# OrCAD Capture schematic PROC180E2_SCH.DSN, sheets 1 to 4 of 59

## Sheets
1 39. DIGITAL AUDIO IN_OUT-2: size C; title: AUDIO -  DIGITAL IN & OUT, OPTICAL IN -2; rev: E2
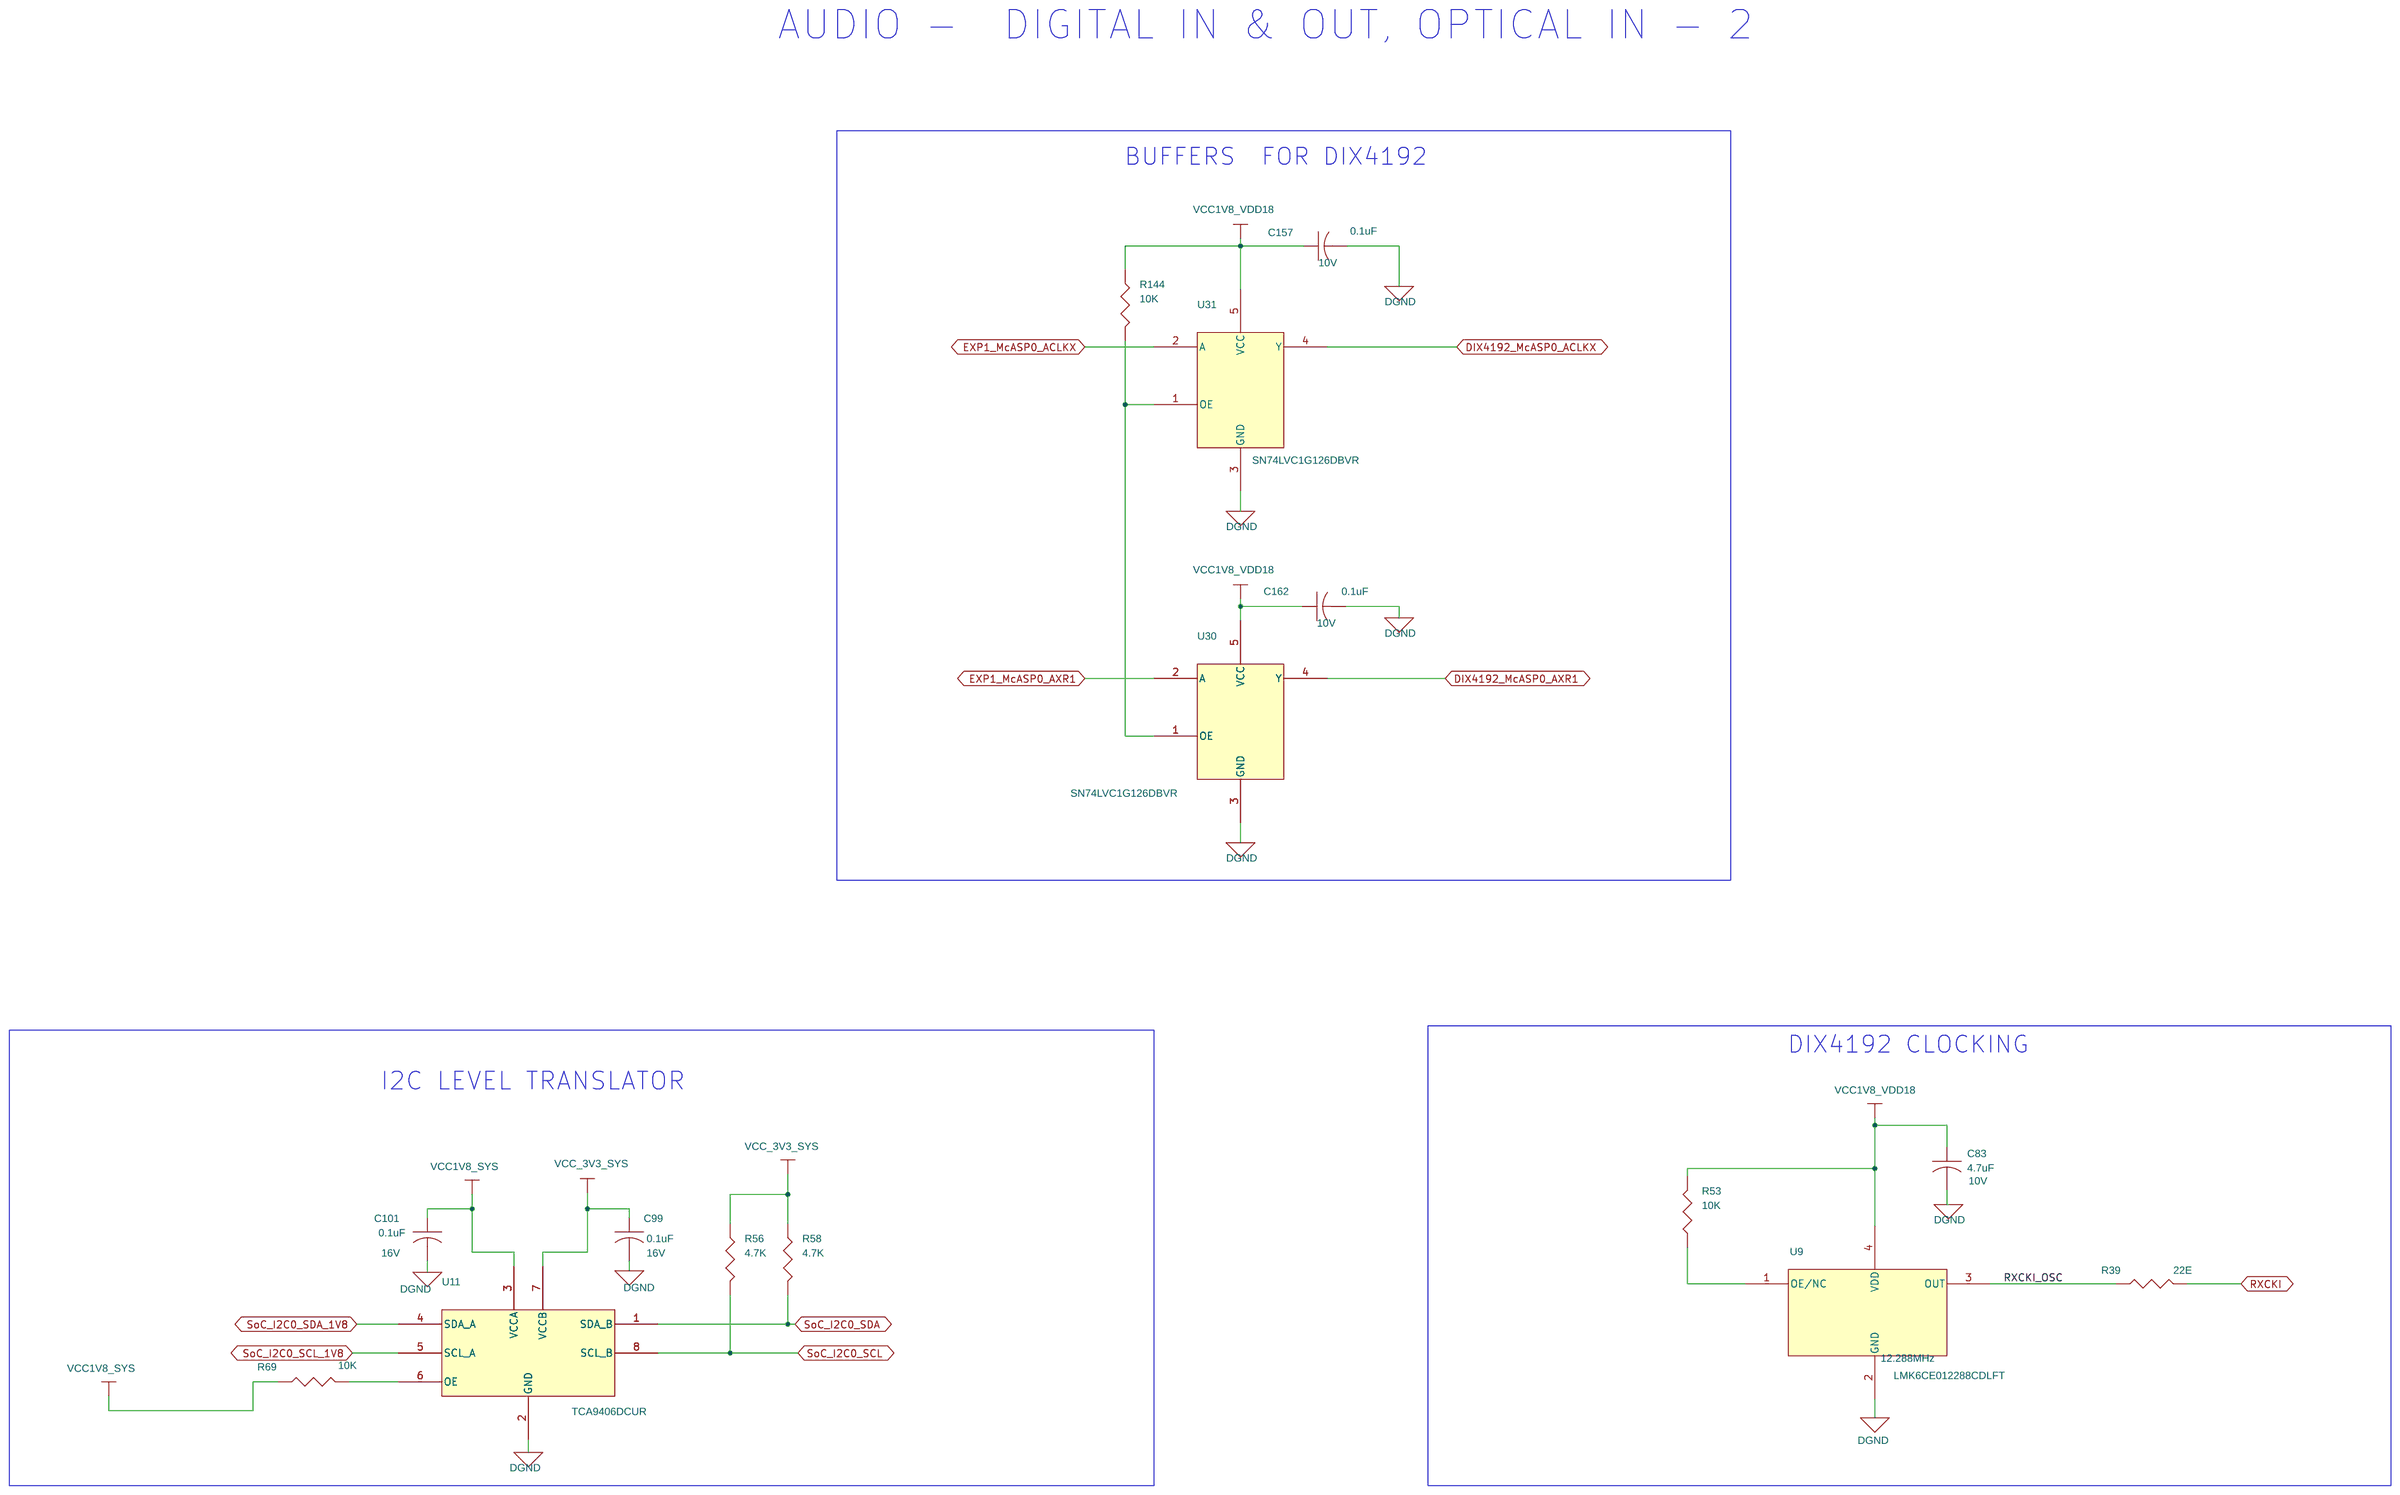
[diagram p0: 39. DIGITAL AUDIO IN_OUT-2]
2 14. SOC POWER SUPPLY PMIC - 2: size C; title: SOC POWER SUPPLY PMIC - 2
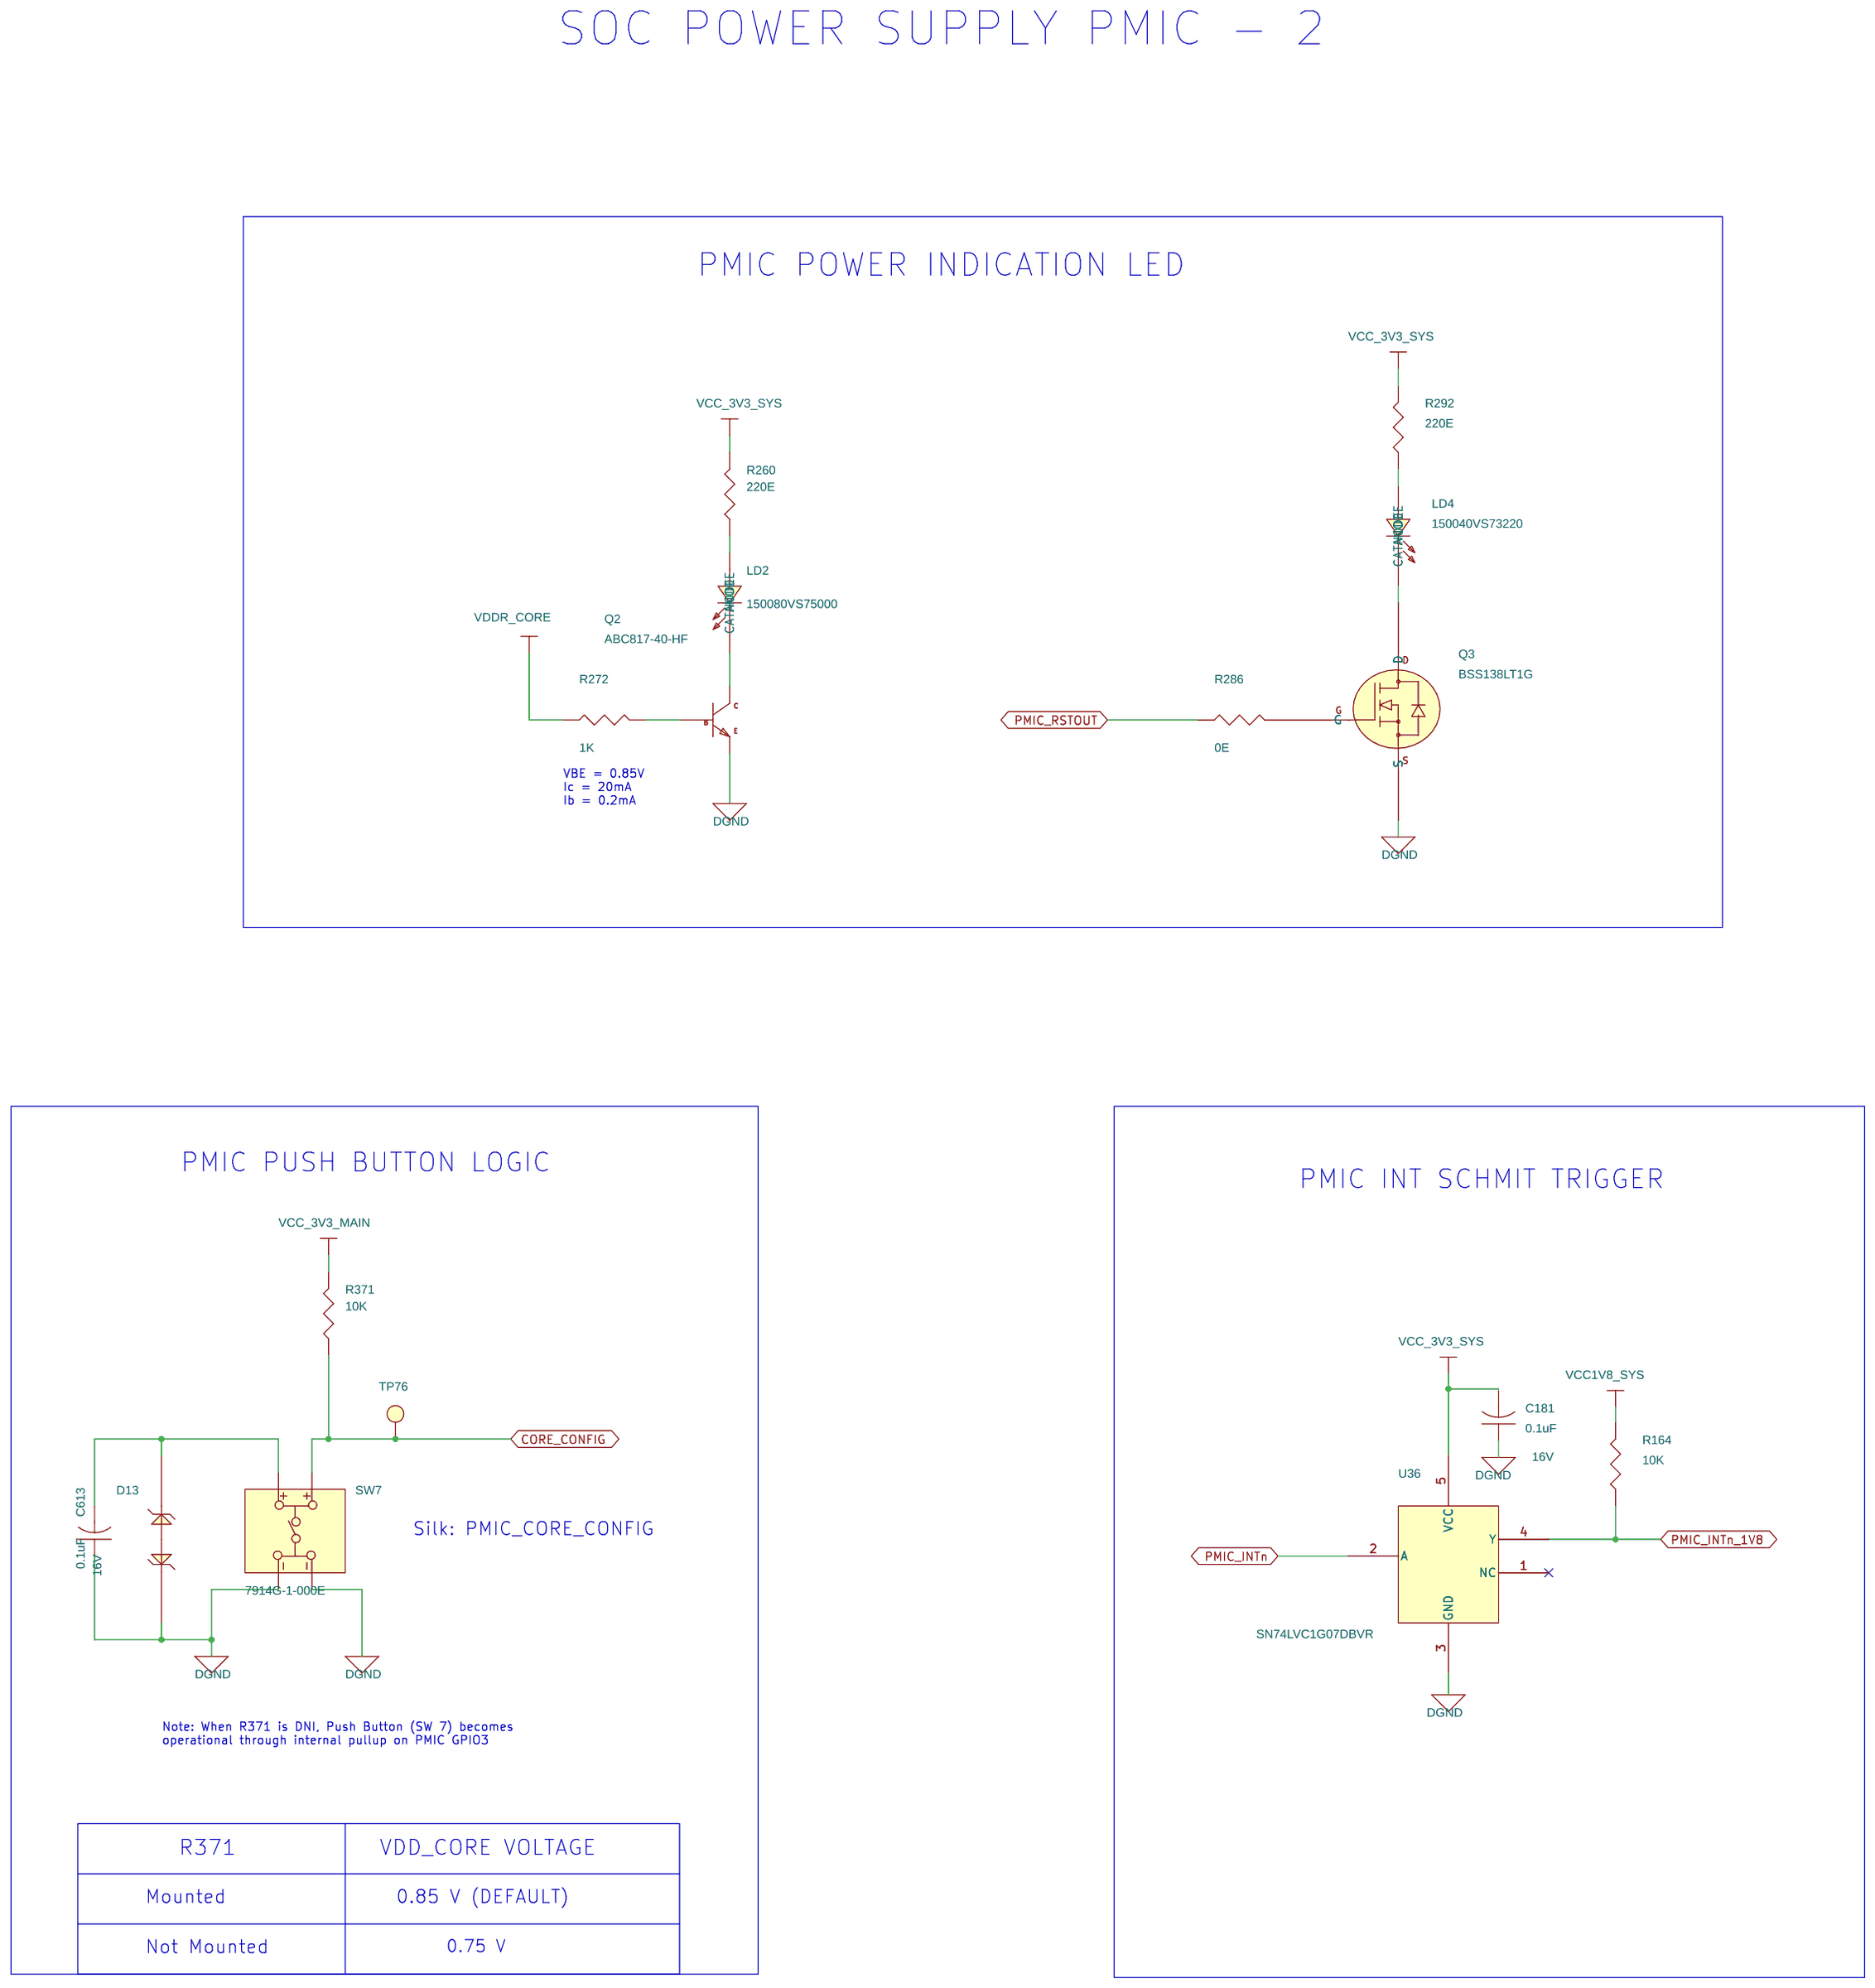
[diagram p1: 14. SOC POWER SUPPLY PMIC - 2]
3 57. TEST AUTOMATION BUFFERS: size C; title: XDS110 TEST AUTOMATION BUFFERS
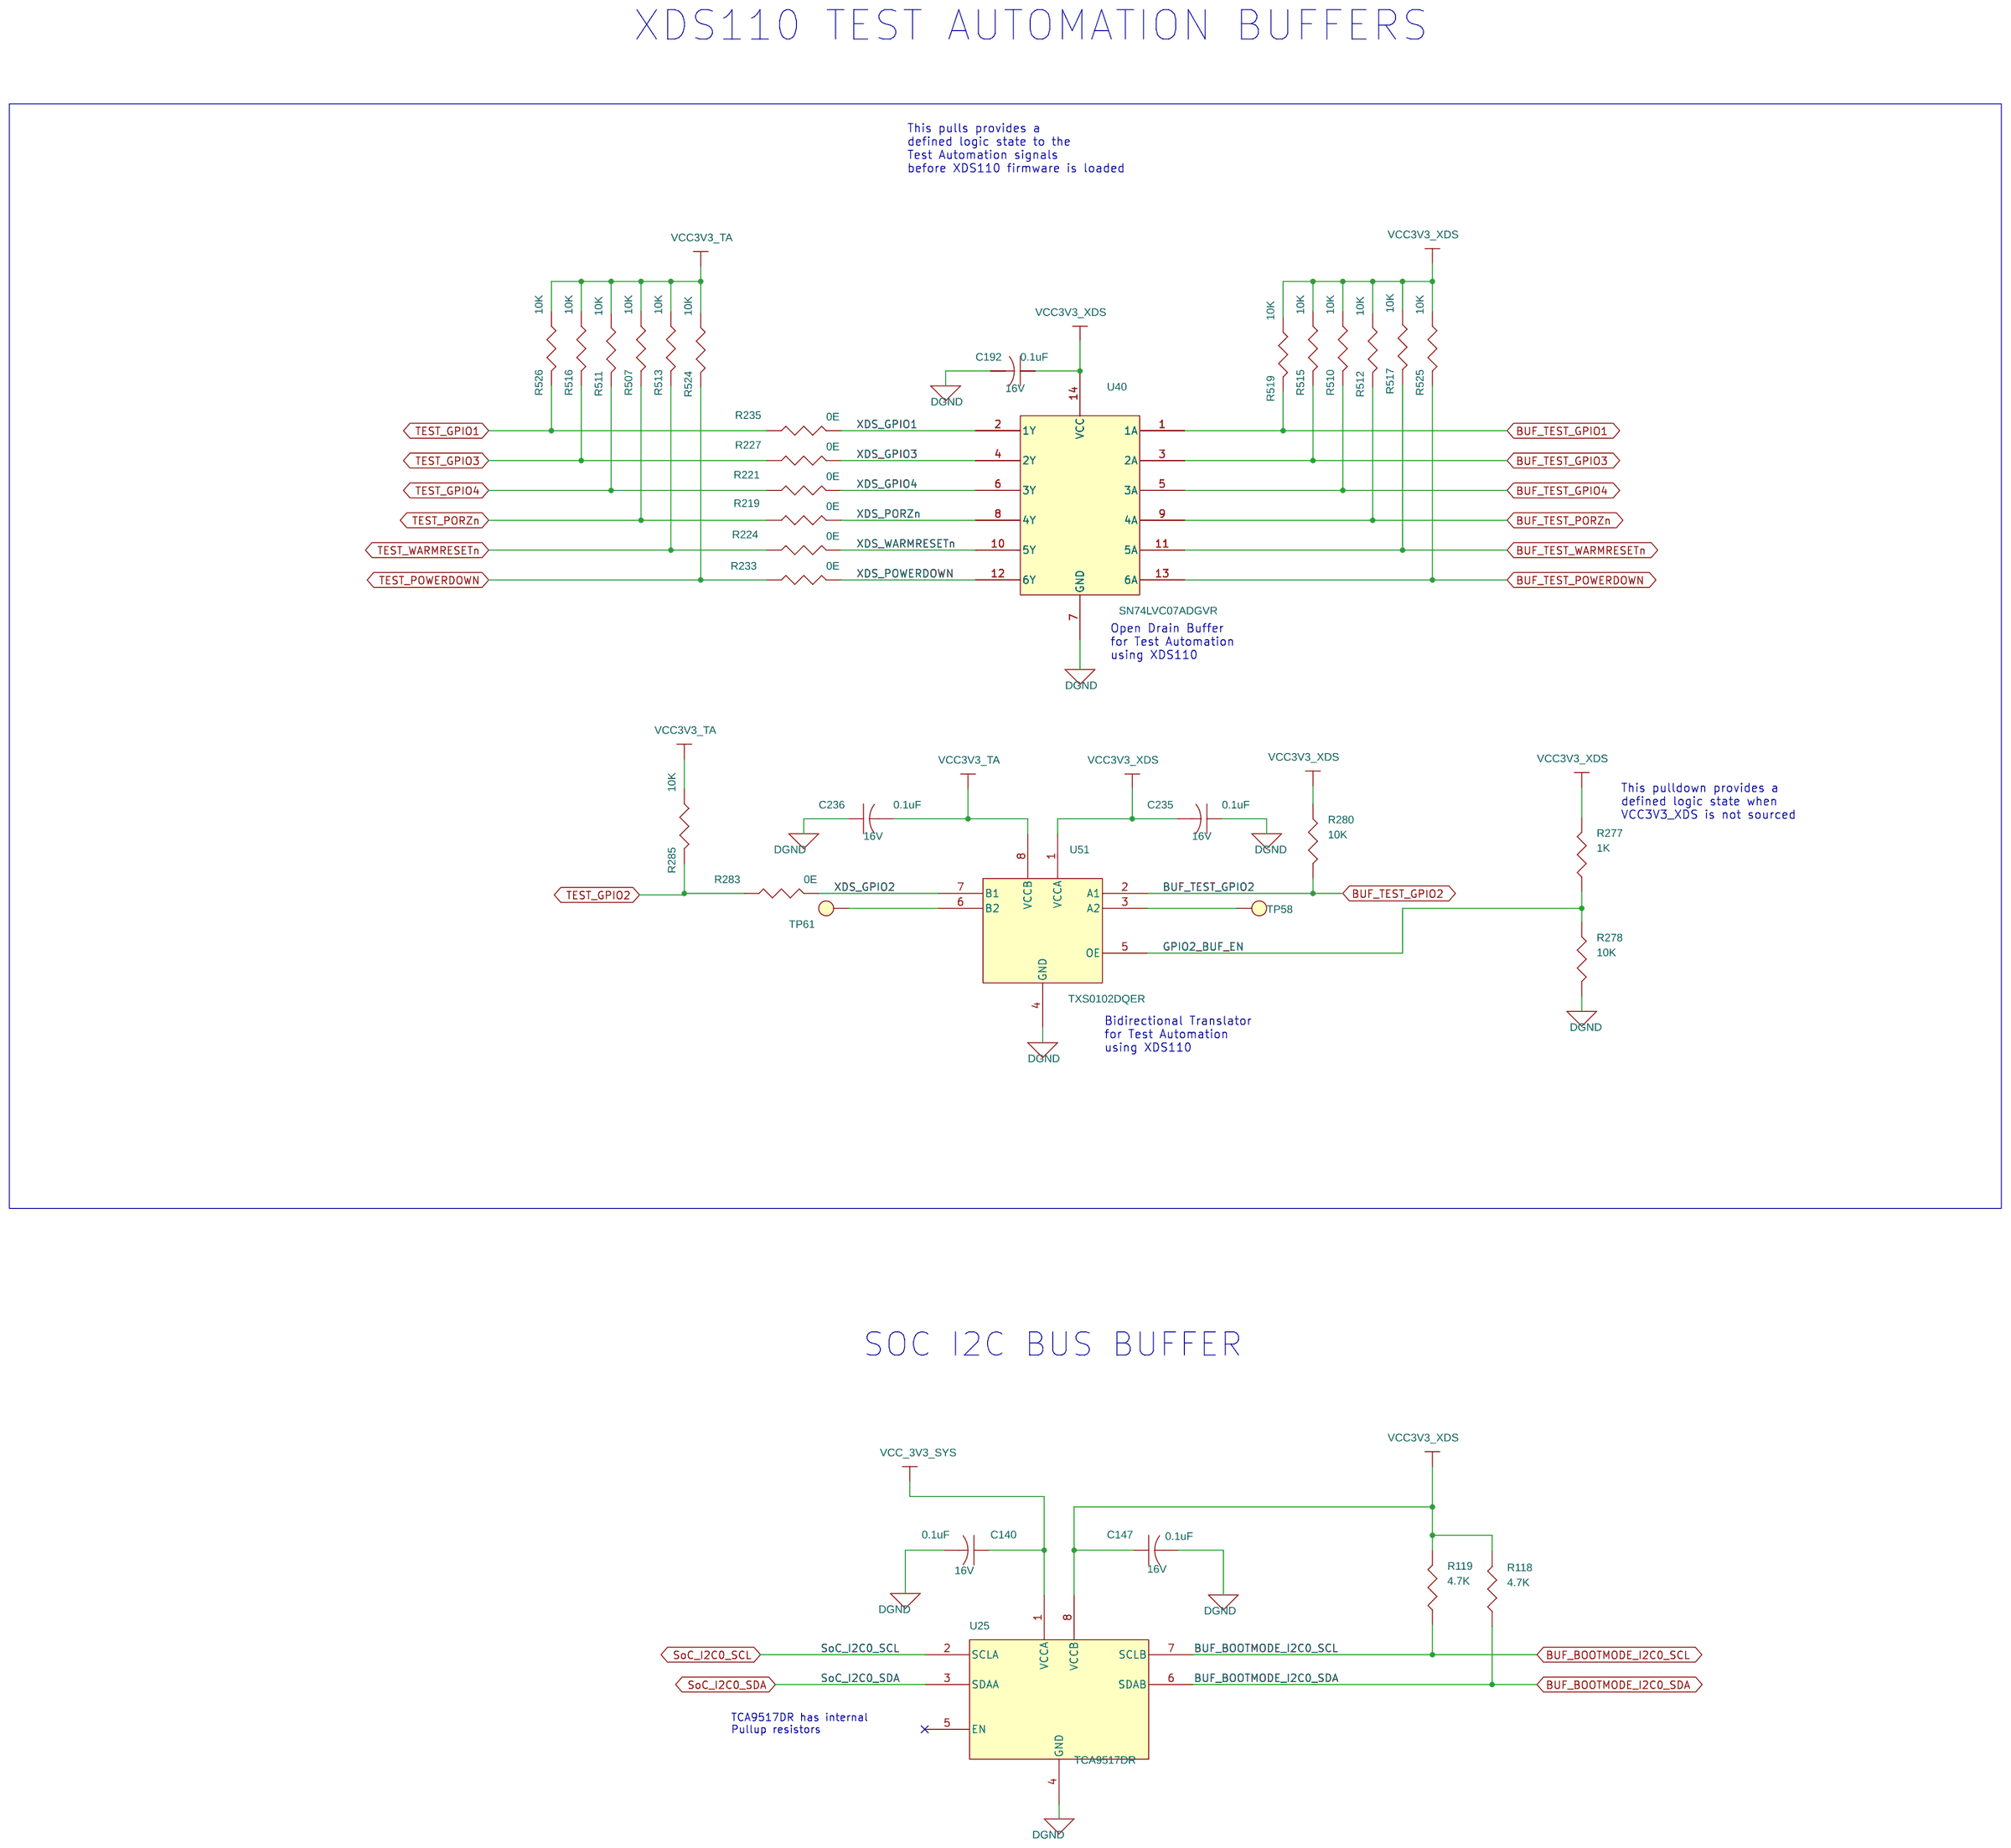
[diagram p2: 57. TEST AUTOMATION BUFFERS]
4 54. FT4232 UART BUFFERS: size C; title: FT4232 UART BUFFERS
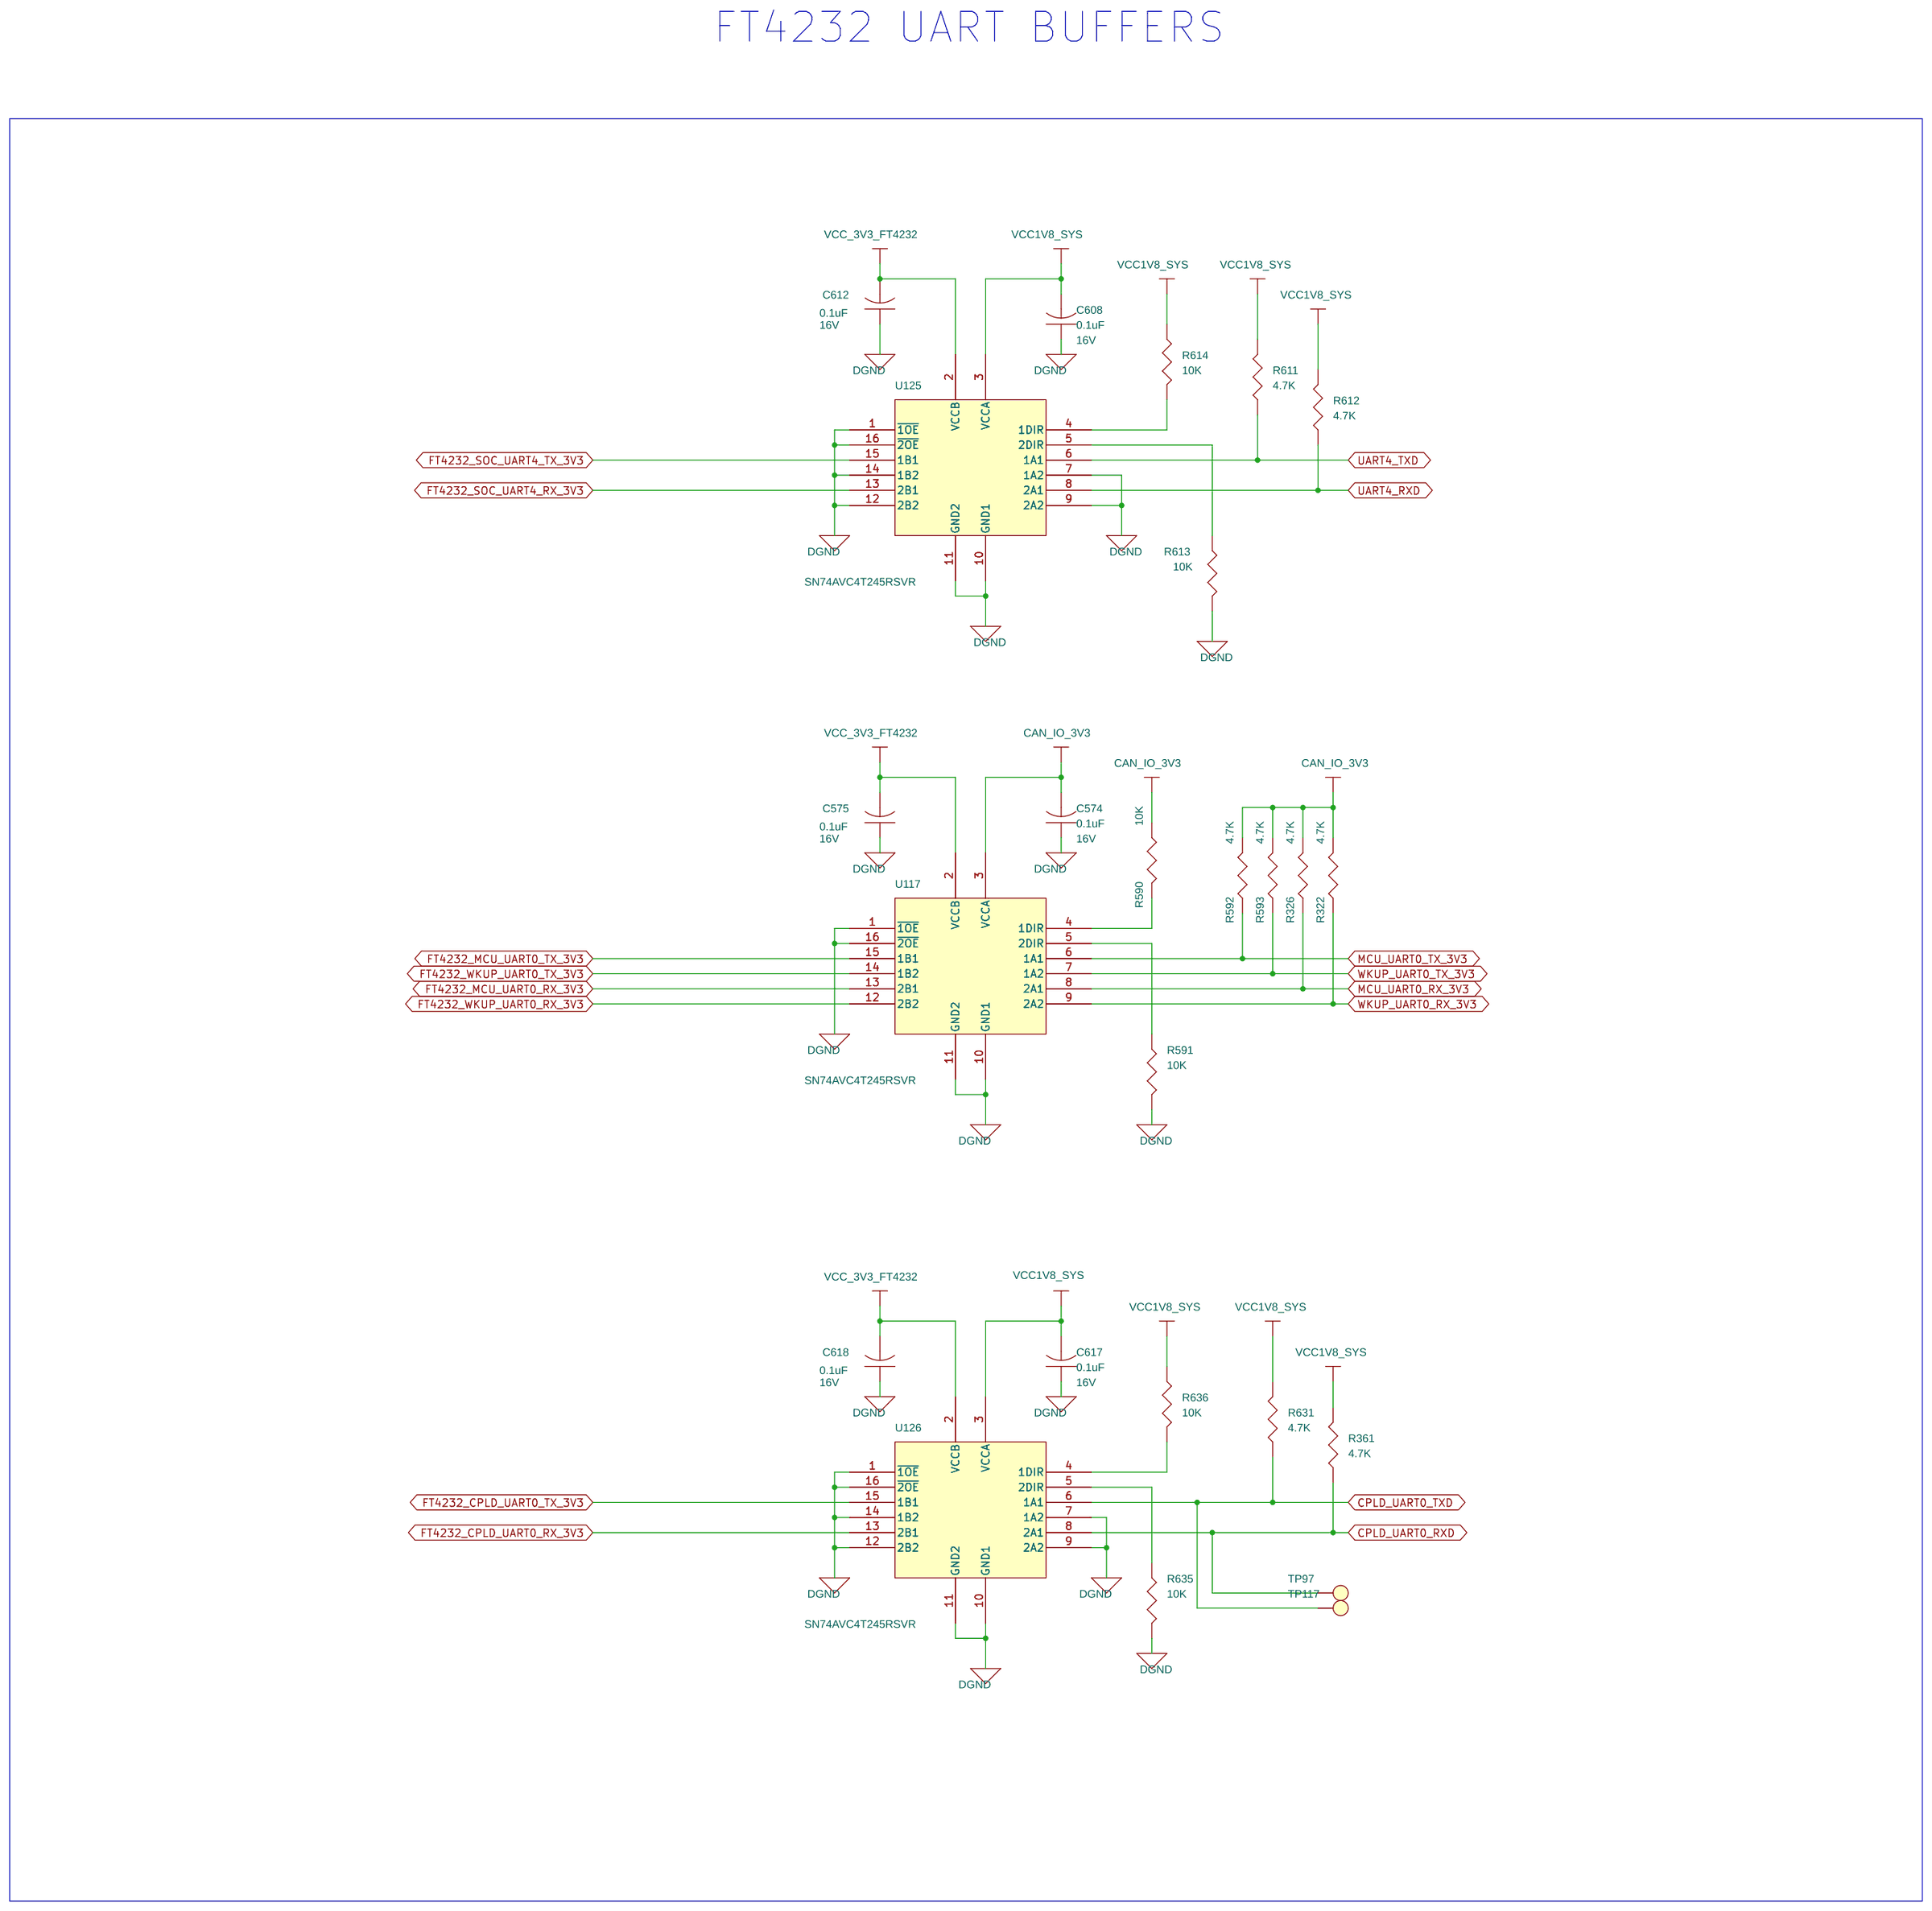
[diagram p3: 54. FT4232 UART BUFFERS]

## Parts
sheet 14. SOC POWER SUPPLY PMIC - 2
C181  0.1uF  [CAP0201_0-5]
C613  0.1uF  [CAP0201_0-5]
D13  TPD1E10B06DPYR  [DIO_DFN0402_0-5]
LD2  150080VS75000  [LED_150080VS75000_80X50_SMD_0-8]
LD4  150040VS73220  [LED_150040GS73220_40X20_SMD_0-4]
Q2  ABC817-40-HF  [SOT23-123_1-2]
Q3  BSS138LT1G  [SOT23-123_1-2]
R164  10K  [RES0402_0-5]
R260  220E  [RES0402_0-5]
R272  1K  [RES0402_0-5]
R286  0E  [RES0201_0-5]
R292  220E  [RES0402_0-5]
R371  10K  [RES0201_0-5]
SW7  7914G-1-000E  [SW4_100X216_200X200_SMD_4-2]
TP76  TP20_SMD  [TP20_SMD]
U36  SN74LVC1G07DBVR  [SOT23-5]
sheet 39. DIGITAL AUDIO IN_OUT-2
C83  4.7uF  [CAP0402_0-75]
C99  0.1uF  [CAP0201_0-5]
C101  0.1uF  [CAP0201_0-5]
C157  0.1uF  [CAP0402_0-75]
C162  0.1uF  [CAP0402_0-75]
R39  22E  [RES0201_0-5]
R53  10K  [RES0201_0-5]
R56  4.7K  [RES0201_0-5]
R58  4.7K  [RES0201_0-5]
R69  10K  [RES0402_0-5]
R144  10K  [RES0201_0-5]
U9  12.288MHz  [VSON4_LMK6CE_80X100_SMD_1]
U11  TCA9406DCUR  [VSSOP8_19-68_85X95]
U30  SN74LVC1G126DBVR  [SOT23-5_1-5]
U31  SN74LVC1G126DBVR  [SOT23-5_1-5]
sheet 54. FT4232 UART BUFFERS
C574  0.1uF  [CAP0201_0-5]
C575  0.1uF  [CAP0201_0-5]
C608  0.1uF  [CAP0201_0-5]
C612  0.1uF  [CAP0201_0-5]
C617  0.1uF  [CAP0201_0-5]
C618  0.1uF  [CAP0201_0-5]
R322  4.7K  [RES0201_0-5]
R326  4.7K  [RES0201_0-5]
R361  4.7K  [RES0201_0-5]
R590  10K  [RES0201_0-5]
R591  10K  [RES0201_0-5]
R592  4.7K  [RES0201_0-5]
R593  4.7K  [RES0201_0-5]
R611  4.7K  [RES0201_0-5]
R612  4.7K  [RES0201_0-5]
R613  10K  [RES0201_0-5]
R614  10K  [RES0201_0-5]
R631  4.7K  [RES0201_0-5]
R635  10K  [RES0201_0-5]
R636  10K  [RES0201_0-5]
TP97  TP20_SMD  [TP20_SMD]
TP117  TP20_SMD  [TP20_SMD]
U117  SN74AVC4T245RSVR  [UQFN16_TMUX1574_70X100_0-6]
U125  SN74AVC4T245RSVR  [UQFN16_TMUX1574_70X100_0-6]
U126  SN74AVC4T245RSVR  [UQFN16_TMUX1574_70X100_0-6]
sheet 57. TEST AUTOMATION BUFFERS
C140  0.1uF  [CAP0201_0-5]
C147  0.1uF  [CAP0201_0-5]
C192  0.1uF  [CAP0201_0-5]
C235  0.1uF  [CAP0201_0-5]
C236  0.1uF  [CAP0201_0-5]
R118  4.7K  [RES0201_0-5]
R119  4.7K  [RES0201_0-5]
R219  0E  [RES0201_0-5]
R221  0E  [RES0201_0-5]
R224  0E  [RES0201_0-5]
R227  0E  [RES0201_0-5]
R233  0E  [RES0201_0-5]
R235  0E  [RES0201_0-5]
R277  1K  [RES0402_0-5]
R278  10K  [RES0201_0-5]
R280  10K  [RES0201_0-5]
R283  0E  [RES0201_0-5]
R285  10K  [RES0201_0-5]
R507  10K  [RES0201_0-5]
R510  10K  [RES0201_0-5]
R511  10K  [RES0201_0-5]
R512  10K  [RES0201_0-5]
R513  10K  [RES0201_0-5]
R515  10K  [RES0201_0-5]
R516  10K  [RES0201_0-5]
R517  10K  [RES0201_0-5]
R519  10K  [RES0201_0-5]
R524  10K  [RES0201_0-5]
R525  10K  [RES0201_0-5]
R526  10K  [RES0201_0-5]
TP58  TP20_SMD  [TP20_SMD]
TP61  TP20_SMD  [TP20_SMD]
U25  TCA9517DR  [SOIC8_1-8]
U40  SN74LVC07ADGVR  [TVSOP14_15-74_180X150_1-2]
U51  TXS0102DQER  [X2SON8_TXS0102_40X60_0-4]

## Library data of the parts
C140 C147 C181 C192 C235 C236 C574 C575 C608 C612 C613 C617 C618 = CAP: CAP CERAMIC 0.1uF 16V 10% X7S AUTO 0201; Alt_Mfr_name: YAGEO AMERICA; Alt_Mfr_part_number: CC0402KRX5R8BB104; Chkd/date: MANIRAJA/110321; Crtd /date: ALVY/110321; Custom_Duty: 15%; Customs_HS_Code: 85322990; Distributor_name: DIGIKEY; Distributor_part_number: 490-GRT033C71C104KE01DTR-ND; Footprint Path: Y:\MIS_DATABASE\Library\ALTIUM_TOOL\PCB_FOOTPRINTS\Altium_Footprint_Lib.PcbLib; Height: 0.33MM; Library Path: Y:\MIS_DATABASE\Library\ALTIUM_TOOL\SCHEMATICS_PARTS\MS_DISCRETE_Library.schlib; Mfr_name: MURATA; Mfr_part_number: GRT033C71C104KE01D; Mistral Part No: 120021030007-R; Package: 0201; Part_type: CAPACITORS\CERAMIC; Project: J7ES_SK_BRD; RoHS: RoHS; Temperature: -55°C+125°C; Tolerance: 10%; Voltage: 16V; Wattage: NA; Weight: 330mg; Datasheet: Y:\MIS_DATABASE\DATASHEETS\CAPACITORS\GRT033C71C104KE01.PDF
D13 = DIODE_SOD323: DIODE 1CH ESD PROTECTION X1SON2; Chkd/date: MANIRAJA/040420; Crtd /date: VASANTHA/181114; Custom_Duty: 15%; Customs_HS_Code: 85423100; Distributor_name: DIGIKEY; Distributor_part_number: 296-30406-1-ND; Footprint Path: Y:\MIS_DATABASE\Library\ALTIUM_TOOL\PCB_FOOTPRINTS\Altium_Footprint_Lib.PcbLib; Height: 0.45MM; Library Path: Y:\MIS_DATABASE\Library\ALTIUM_TOOL\SCHEMATICS_PARTS\MS_DISCRETE_Library.schlib; Mfr_name: TEXAS INSTRUMENTS; Mistral Part No: 130014110022-R; Package: X1SON2; Part_type: DIODE; Project: GALILEO_EVM; RoHS: RoHS; Temperature: -40°C+125°C; Tolerance: NA; Voltage: NA; Wattage: NA; Weight: 1mg; Datasheet: Y:\MIS_DATABASE\DATASHEETS\ICS\INTERFACE\TPD1E10B06-SER.PDF
LD2 = DIODE_LED: DIODE LED BRIGHT GREEN SMD; Chkd/date: MANIRAJA/180820; Crtd /date: ALVY/180820; Custom_Duty: 24%; Customs_HS_Code: 85439000; Distributor_name: DIGIKEY; Distributor_part_number: 732-4986-1-ND; Footprint Path: Y:\MIS_DATABASE\Library\ALTIUM_TOOL\PCB_FOOTPRINTS\Altium_Footprint_Lib.PcbLib; Height: 0.80MM; Library Path: Y:\MIS_DATABASE\Library\ALTIUM_TOOL\SCHEMATICS_PARTS\MS_OPTO_Library.schlib; Mfr_name: WURTH ELECTRONICS; Mistral Part No: 130020080012-R; Package: SMD; Part_type: OPTO\LED; Project: AM64x_EVM_BRD; RoHS: RoHS; Temperature: -40°C+85°C; Tolerance: NA; Voltage: NA; Wattage: NA; Weight: 10mg; Datasheet: Y:\MIS_DATABASE\DATASHEETS\DISCRETES\LEDS\150080VS75000.PDF
LD4 = DIODE_LED: DIODE LED BRIGHT GREEN SMD; Chkd/date: MANIRAJA/261120; Crtd /date: ALVY/261120; Custom_Duty: 24%; Customs_HS_Code: 85439000; Distributor_name: DIGIKEY; Distributor_part_number: 732-13425-1-ND; Footprint Path: Y:\MIS_DATABASE\Library\ALTIUM_TOOL\PCB_FOOTPRINTS\Altium_Footprint_Lib.PcbLib; Height: 0.35MM; Library Path: Y:\MIS_DATABASE\Library\ALTIUM_TOOL\SCHEMATICS_PARTS\MS_OPTO_Library.schlib; Mfr_name: WURTH ELECTRONIK; Mistral Part No: 130020110071-R; Package: SMD; Part_type: OPTO\LED; Project: AM64X_SKEVM; RoHS: RoHS; Temperature: -40°C+85°C; Tolerance: NA; Voltage: NA; Wattage: NA; Weight: 29.3mg; Datasheet: Y:\MIS_DATABASE\DATASHEETS\DISCRETES\LEDS\150040VS73220.PDF
Q2 = NPN_123_SOT23-3: TRANSISTOR 45V 500mA NPN GENERAL PURPOSE SOT23-3; Chkd/date: PRAVEEN/260822; Crtd /date: PRAVEEN/260822; Custom_Duty: 15%; Customs_HS_Code: 85423100; Distributor_name: MOUSER; Distributor_part_number: 750-ABC817-40-HF; Footprint Path: Y:\MIS_DATABASE\Library\ALTIUM_TOOL\PCB_FOOTPRINTS\Altium_Footprint_Lib.PcbLib; Height: 1.20MM; Library Path: Y:\MIS_DATABASE\Library\ALTIUM_TOOL\SCHEMATICS_PARTS\MS_MOSFET_Library.schlib; Mfr_name: COMCHIP; Mistral Part No: 142022080040-R; Package: TO-252-3; Part_type: TRANSISTOR\BJT; Project: MS_TI_TMDS64SKEVM; RoHS: RoHS; Temperature: -55°C+150°C; Tolerance: NA; Voltage: 45V; Wattage: NA; Weight: NA; Datasheet: Y:\MIS_DATABASE\DATASHEETS\DISCRETES\TRANSISTORS_FETS\ABC817-40-HF.PDF
Q3 = MOSFET_BSS138W: IC MOSFET N-CHANNEL 50V 200mA SOT23-3; Chkd/date: MANIRAJA/250219; Crtd /date: JEBRAN/060416; Custom_Duty: 15%; Customs_HS_Code: 85423100; Distributor_name: DIGIKEY; Distributor_part_number: BSS138LT1GOSCT-ND; Footprint Path: Y:\MIS_DATABASE\Library\ALTIUM_TOOL\PCB_FOOTPRINTS\Altium_Footprint_Lib.PcbLib; Height: 1.11MM; Library Path: Y:\MIS_DATABASE\Library\ALTIUM_TOOL\SCHEMATICS_PARTS\MS_MOSFET_Library.schlib; Mfr_name: ON SEMICONDUCTOR; Mistral Part No: 142016040001-R; Package: SOT23-3; Part_type: ICS\POWER\MOSFET; Project: LRDE_ABCM; RoHS: RoHS; Temperature: -55°C+150°C; Tolerance: NA; Voltage: NA; Wattage: NA; Weight: 8mg; Datasheet: Y:\MIS_DATABASE\DATASHEETS\DISCRETES\TRANSISTORS_FETS\BSS138LT1G.PDF
R69 R164 = RESISTOR: RES 10K 1/16W 5% 0402; Assembly_Instruction: DNI; Chkd/date: VASANTHA/061216; Crtd /date: MAZHAR/230805; Custom_Duty: 15%; Customs_HS_Code: 85332119; Distributor_name: DIGIKEY; Distributor_part_number: 311-10KJRCT-ND; Footprint Path: Y:\MIS_DATABASE\Library\ALTIUM_TOOL\PCB_FOOTPRINTS\Altium_Footprint_Lib.PcbLib; Height: 0.40MM; Library Path: Y:\MIS_DATABASE\Library\ALTIUM_TOOL\SCHEMATICS_PARTS\MS_DISCRETE_Library.schlib; Mfr_name: YAGEO AMERICA; Mfr_part_number: RC0402JR-0710KL; Mistral Part No: 110011060021-R; Package: 0402; Part_type: RESISTORS\FIXED; Project: HSE; RoHS: RoHS; Temperature: -55°C+155°C; Tolerance: 5%; Voltage: NA; Wattage: 1/16W; Weight: 0.65mg; Datasheet: Y:\MIS_DATABASE\DATASHEETS\RESISTORS\RCXXXXL-SER_MAR18.PDF
R260 R292 = RESISTOR: RES 220E 1/10W 5% 0402; Chkd/date: VASANTHA/291216; Crtd /date: GEETHA/260406; Custom_Duty: 15%; Customs_HS_Code: 85332119; Distributor_name: DIGIKEY; Distributor_part_number: P220JCT-ND; Footprint Path: Y:\MIS_DATABASE\Library\ALTIUM_TOOL\PCB_FOOTPRINTS\Altium_Footprint_Lib.PcbLib; Height: 0.40MM; Library Path: Y:\MIS_DATABASE\Library\ALTIUM_TOOL\SCHEMATICS_PARTS\MS_DISCRETE_Library.schlib; Mfr_name: PANASONIC-ECG; Mfr_part_number: ERJ-2GEJ221X; Mistral Part No: 110009030506-R; Package: 0402; Part_type: RESISTORS\FIXED; Project: RED EYE; RoHS: RoHS; Temperature: -55°C+155°C; Tolerance: 5%; Voltage: NA; Wattage: 1/10W; Weight: 0.8mg; Datasheet: Y:\MIS_DATABASE\DATASHEETS\RESISTORS\PAN-ERJSER_NOV17.PDF
R272 R277 = RESISTOR: RES 1K 1/10W 5% 0402; Chkd/date: VASANTHA/201216; Crtd /date: MAZHAR/230805; Custom_Duty: 15%; Customs_HS_Code: 85332119; Distributor_name: DIGIKEY; Distributor_part_number: P1.0KJCT-ND; Footprint Path: Y:\MIS_DATABASE\Library\ALTIUM_TOOL\PCB_FOOTPRINTS\Altium_Footprint_Lib.PcbLib; Height: 0.40MM; Library Path: Y:\MIS_DATABASE\Library\ALTIUM_TOOL\SCHEMATICS_PARTS\MS_DISCRETE_Library.schlib; Mfr_name: PANASONIC-ECG; Mfr_part_number: ERJ-2GEJ102X; Mistral Part No: 110009030400-R; Package: 0402; Part_type: RESISTORS\FIXED; Project: HSE; RoHS: RoHS; Temperature: -55°C+155°C; Tolerance: 5%; Voltage: NA; Wattage: 1/10W; Weight: 0.8mg; Datasheet: Y:\MIS_DATABASE\DATASHEETS\RESISTORS\PAN-ERJSER_NOV17.PDF
R219 R221 R224 R227 R233 R235 R283 R286 = RESISTOR: RES 0E 1/20W 5% 0201; Chkd/date: NAVEED/301214; Crtd /date: MUDDU/120710; Custom_Duty: 15%; Customs_HS_Code: 85332119; Distributor_name: DIGIKEY; Distributor_part_number: 311-0.0NCT-ND; Footprint Path: Y:\MIS_DATABASE\Library\ALTIUM_TOOL\PCB_FOOTPRINTS\Altium_Footprint_Lib.PcbLib; Height: 0.26MM; Library Path: Y:\MIS_DATABASE\Library\ALTIUM_TOOL\SCHEMATICS_PARTS\MS_DISCRETE_Library.schlib; Mfr_name: YAGEO AMERICA; Mfr_part_number: RC0201JR-070RL; Mistral Part No: 110010070067-R; Package: 0201; Part_type: RESISTORS\FIXED; Project: PB_BUGBASE; RoHS: RoHS; Temperature: -55°C+125°C; Tolerance: 5%; Voltage: NA; Wattage: 1/20W; Weight: 0.17mg; Datasheet: Y:\MIS_DATABASE\DATASHEETS\RESISTORS\RCXXXXL-SER_MAR18.PDF
R53 R144 R278 R280 R285 R371 R507 R510-R513 R515-R517 R519 R524-R526 R590 R591 R613 R614 R635 R636 = RESISTOR: RES 10K 1/20W 5% 0201; Chkd/date: MANIRAJA/050517; Crtd /date: MANIRAJA/050517; Custom_Duty: 15%; Customs_HS_Code: 85332119; Distributor_name: DIGIKEY; Distributor_part_number: 311-10KNCT-ND; Footprint Path: Y:\MIS_DATABASE\Library\ALTIUM_TOOL\PCB_FOOTPRINTS\Altium_Footprint_Lib.PcbLib; Height: 0.26MM; Library Path: Y:\MIS_DATABASE\Library\ALTIUM_TOOL\SCHEMATICS_PARTS\MS_DISCRETE_Library.schlib; Mfr_name: YAGEO AMERICA; Mfr_part_number: RC0201JR-0710KL; Mistral Part No: 110010070051-R; Package: 0201; Part_type: RESISTORS\FIXED; Project: GOLDEN-I LITE; RoHS: RoHS; Temperature: -55°C+125°C; Tolerance: 5%; Voltage: NA; Wattage: 1/20W; Weight: 0.17mg; Datasheet: Y:\MIS_DATABASE\DATASHEETS\RESISTORS\RCXXXXL-SER_MAR18.PDF
SW7 = 7914G-1-000E__7914G: SWITCH SPST-NO 4MM SQ SMD 7914G; Chkd/date: VASANTHA/271216; Crtd /date: BAVISH/051010; Custom_Duty: 24%; Customs_HS_Code: 85369090; Distributor_name: DIGIKEY; Distributor_part_number: 7914G-000ECT-ND; Height: 4.19MM; Library Ref: 7914G-1-000E _7914G; Mfr_name: BOURNS; Mistral Part No: 130015110004-R; Package: 7914G; Part_type: ELECTRO-MECHANICAL\SWITCH; Project: AAAUC; RoHS: RoHS; Temperature: -55°C+125°C; Tolerance: NA; Voltage: NA; Wattage: NA; Weight: NA; Datasheet: Y:\MIS_DATABASE\DATASHEETS\ICS\DIGITAL\COMBINATIONAL\7914G-1-000E.PDF
TP58 TP61 TP76 TP97 TP117 = TESTPOINT: TESTPOINT CIR 20 SMD; Chkd/date: SHREESHAIL/171006; Crtd /date: MAZHAR/171006; Custom_Duty: NA; Customs_HS_Code: NA; Distributor_name: NA; Distributor_part_number: NA; Footprint Path: Y:\MIS_DATABASE\Library\ALTIUM_TOOL\PCB_FOOTPRINTS\Altium_Footprint_Lib.PcbLib; Height: NA; Library Path: Y:\MIS_DATABASE\Library\ALTIUM_TOOL\SCHEMATICS_PARTS\MS_DISCRETE_Library.schlib; MECHANICAL 3D STEP FILE: NA; Mfr_name: LOCAL; Mistral Part No: NA; Package: SMD; Project: BT MODULE_CSRBC04; RoHS: NA; Temperature: NA; Tolerance: NA; Voltage: NA; Wattage: NA; Weight: NA; Datasheet: NA
U36 = SN74LVC1G07DBVR_SOT23-5: IC SINGLE BUFFER/DRIVER SOT23-5; Chkd/date: MAZHAR/200208; Crtd /date: USMAN/200208; Custom_Duty: 15%; Customs_HS_Code: 85423100; Distributor_name: DIGIKEY; Distributor_part_number: 296-8485-1-ND; Footprint Path: Y:\MIS_DATABASE\Library\ALTIUM_TOOL\PCB_FOOTPRINTS\Altium_Footprint_Lib.PcbLib; Height: 1.45MM; Junction to Board °C/W: 62; Junction to Case °C/W: 164; Mfr_name: TEXAS INSTRUMENTS; Mistral Part No: 141009030405-R; Part_type: ICS\INTERFACE\LINE DRIVER; Project: MIB; RoHS: Sb/ Br FREE; Datasheet: Y:\MIS_DATABASE\DATASHEETS\ICS\INTERFACE\SN74LVC1G07.PDF
C83 = CAP: CAP CERAMIC 4.7uF 10V 20% X5R AUTO 0402; Chkd/date: MANIRAJA/250221; Crtd /date: ALVY/240221; Custom_Duty: 15%; Customs_HS_Code: 85322990; Distributor_name: MOUSER; Distributor_part_number: 81-GRT155R61A475ME13; Footprint Path: Y:\MIS_DATABASE\Library\ALTIUM_TOOL\PCB_FOOTPRINTS\Altium_Footprint_Lib.PcbLib; Height: 0.65MM; Library Path: Y:\MIS_DATABASE\Library\ALTIUM_TOOL\SCHEMATICS_PARTS\MS_DISCRETE_Library.schlib; Mfr_name: MURATA; Mfr_part_number: GRT155R61A475ME13D; Mistral Part No: 120021020032-R; Package: 0402; Part_type: CAPACITORS\CERAMIC; Project: TI_DRA821 SK EVM BRD; RoHS: RoHS; Temperature: -55°C+85°C; Tolerance: 20%; Voltage: 10V; Wattage: NA; Weight: 1.5mg; Datasheet: Y:\MIS_DATABASE\DATASHEETS\CAPACITORS\GRT155R61A475ME13.PDF
C99 C101 = CAP: CAP CERAMIC 0.1uF 16V 10% X7S AUTO 0201; Chkd/date: MANIRAJA/110321; Crtd /date: ALVY/110321; Custom_Duty: 15%; Customs_HS_Code: 85322990; Distributor_name: DIGIKEY; Distributor_part_number: 490-GRT033C71C104KE01DTR-ND; Footprint Path: Y:\MIS_DATABASE\Library\ALTIUM_TOOL\PCB_FOOTPRINTS\Altium_Footprint_Lib.PcbLib; Height: 0.33MM; Library Path: Y:\MIS_DATABASE\Library\ALTIUM_TOOL\SCHEMATICS_PARTS\MS_DISCRETE_Library.schlib; Mfr_name: MURATA; Mfr_part_number: GRT033C71C104KE01D; Mistral Part No: 120021030007-R; Package: 0201; Part_type: CAPACITORS\CERAMIC; Project: J7ES_SK_BRD; RoHS: RoHS; Temperature: -55°C+125°C; Tolerance: 10%; Voltage: 16V; Wattage: NA; Weight: 330mg; Datasheet: Y:\MIS_DATABASE\DATASHEETS\CAPACITORS\GRT033C71C104KE01.PDF
C157 C162 = CAP: CAP CERAMIC 0.1uF 50V 10% X7R AUTO 0402; Chkd/date: MANIRAJA/250221; Crtd /date: ALVY/240221; Custom_Duty: 15%; Customs_HS_Code: 85322990; Distributor_name: MOUSER; Distributor_part_number: 81-GRT155R71H104KE1D; Footprint Path: Y:\MIS_DATABASE\Library\ALTIUM_TOOL\PCB_FOOTPRINTS\Altium_Footprint_Lib.PcbLib; Height: 0.55MM; Library Path: Y:\MIS_DATABASE\Library\ALTIUM_TOOL\SCHEMATICS_PARTS\MS_DISCRETE_Library.schlib; Mfr_name: MURATA; Mfr_part_number: GRT155R71H104KE01D; Mistral Part No: 120019030005-R; Package: 0402; Part_type: CAPACITORS\CERAMIC; Project: TI_DRA821 SK EVM BRD; RoHS: RoHS; Temperature: -55°C+125°C; Tolerance: 10%; Voltage: 10V; Wattage: NA; Weight: NA; Datasheet: Y:\MIS_DATABASE\DATASHEETS\CAPACITORS\GRT155R71H104KE01.PDF
R39 = RESISTOR: RES 22E 1/20W 5% 0201; Chkd/date: ALVY/210122; Crtd /date: TAMILARASU/210122; Custom_Duty: 15%; Customs_HS_Code: 85332119; Distributor_name: DIGIKEY; Distributor_part_number: 541-22AGCT-ND; Footprint Path: Y:\MIS_DATABASE\Library\ALTIUM_TOOL\PCB_FOOTPRINTS\Altium_Footprint_Lib.PcbLib; Height: 0.28MM; Library Path: Y:\MIS_DATABASE\Library\ALTIUM_TOOL\SCHEMATICS_PARTS\MS_DISCRETE_Library.schlib; Mfr_name: VISHAY; Mfr_part_number: CRCW020122R0JNED; Mistral Part No: 110022010021-R; Package: 0201; Part_type: RESISTORS\FIXED; Project: DLRL DIGITAL RECEIVER_BRD; RoHS: RoHS; Temperature: -55°C+155°C; Tolerance: 5%; Voltage: NA; Wattage: 1/20W; Weight: 0.17mg; Datasheet: Y:\MIS_DATABASE\DATASHEETS\RESISTORS\CRCW0201.PDF
R56 R58 R118 R119 R322 R326 R361 R592 R593 R611 R612 R631 = RESISTOR: RES 4.7K 1/20W 5% 0201; Chkd/date: MANIRAJA/200921; Crtd /date: ALVY/200921; Custom_Duty: 15%; Customs_HS_Code: 85332119; Distributor_name: DIGIKEY; Distributor_part_number: 311-4.7KNCT-ND; Footprint Path: Y:\MIS_DATABASE\Library\ALTIUM_TOOL\PCB_FOOTPRINTS\Altium_Footprint_Lib.PcbLib; Height: 0.26MM; Library Path: Y:\MIS_DATABASE\Library\ALTIUM_TOOL\SCHEMATICS_PARTS\MS_DISCRETE_Library.schlib; Mfr_name: YAGEO AMERICA; Mfr_part_number: RC0201JR-074K7L; Mistral Part No: 110021090007-R; Package: 0201; Part_type: RESISTORS\FIXED; Project: TI_AM62x SKEVM_BRD; RoHS: RoHS; Temperature: -55°C+125°C; Tolerance: 5%; Voltage: NA; Wattage: 1/20W; Weight: 0.17mg; Datasheet: Y:\MIS_DATABASE\DATASHEETS\RESISTORS\RCXXXXL-SER_MAR18.PDF
U9 = OSC4_LMK6CE: OSC 12.288MHz LOW JITTER HIGH-PERFORMANCE BAW VSON4; Chkd/date: PRAVEEN/170423; Crtd /date: TAMILARASU/170423; Custom_Duty: 15%; Customs_HS_Code: 85412900; Distributor_name: NA; Distributor_part_number: NA; Height: 1.00MM; Mfr_name: TEXAS INSTRUMENTS; Mfr_part_number: LMK6CE012288CDLFT; Mistral Part No: 130023040013-R; Package: VSON4; Part_type: OSCILLATORS; Project: AM62P_SK; RoHS: RoHS; Temperature: -40°C+105°C; Tolerance: NA; Voltage: NA; Wattage: NA; Weight: NA; Datasheet: Y:\MIS_DATABASE\DATASHEETS\MISC\CRY_OSC\LMK6CXXX-SER.PDF
U11 = TCA9406DCUR_VSSOP8: IC VOLTAGE-LEVEL TRANSLATOR 2BIT BIDIRECTIONAL VSSOP8; Chkd/date: USMAN/190612; Crtd /date: BAVISH/210611; Custom_Duty: 15%; Customs_HS_Code: 85423100; Distributor_name: DIGIKEY; Distributor_part_number: 296-28109-1-ND; Footprint Path: Y:\MIS_DATABASE\Library\ALTIUM_TOOL\PCB_FOOTPRINTS\Altium_Footprint_Lib.PcbLib; Height: 0.90MM; Library Path: Y:\MIS_DATABASE\Library\ALTIUM_TOOL\SCHEMATICS_PARTS\MS_MISCINTERFACE_Library.schlib; Mfr_name: TEXAS INSTRUMENTS; Mistral Part No: 141011060026-R; Package: VSSOP8; Part_type: ICS\INTERFACE; Project: SVDU; RoHS: RoHS; Temperature: -40°C+85°C; Tolerance: NA; Voltage: NA; Wattage: NA; Weight: NA; Datasheet: Y:\MIS_DATABASE\DATASHEETS\ICS\INTERFACE\TCA9406.PDF
U30 U31 = SN74LVC1G126DBVR_SOT23-5: IC SINGLE BUS BUFFER GATE WITH 3-STATE O/P SOT23-5; Chkd/date: MANIRAJA/130519; Crtd /date: MAZHAR/301106; Custom_Duty: 15%; Customs_HS_Code: 85423100; Distributor_name: DIGIKEY; Distributor_part_number: 296-11605-1-ND; Footprint Path: Y:\MIS_DATABASE\Library\ALTIUM_TOOL\PCB_FOOTPRINTS\Altium_Footprint_Lib.PcbLib; Height: 1.45MM; Library Path: Y:\MIS_DATABASE\Library\ALTIUM_TOOL\SCHEMATICS_PARTS\MS_GATE_Library.schlib; Mfr_name: TEXAS INSTRUMENTS; Mistral Part No: 141009030232-R; Package: SOT23-5; Part_type: ICS\DIGITAL\GATES; Project: PMP LCD BOARD; RoHS: RoHS; Temperature: -40°C+125°C; Tolerance: NA; Voltage: NA; Wattage: NA; Weight: 6.3mg; Datasheet: Y:\MIS_DATABASE\DATASHEETS\ICS\DIGITAL\GATES\SN74LVC1G126XXX.PDF
U117 U125 U126 = SN74AVC4T245RSV_UQFN16: IC 2-BIT BUS TRANSCEIVER WITH CONFIGURABLE VOLTAGE TRANSLATION AND 3 STATE O/P UQFN16; Chkd/date: MANIRAJA/040520; Crtd /date: BAVISH/190411; Custom_Duty: 15%; Customs_HS_Code: 85423100; Distributor_name: DIGIKEY; Distributor_part_number: 296-24366-1-ND; Footprint Path: Y:\MIS_DATABASE\Library\ALTIUM_TOOL\PCB_FOOTPRINTS\Altium_Footprint_Lib.PcbLib; Height: 0.55MM; Library Path: Y:\MIS_DATABASE\Library\ALTIUM_TOOL\SCHEMATICS_PARTS\MS_BUSDRIVERTRANSCEIVER_Library.schlib; Mfr_name: TEXAS INSTRUMENTS; Mistral Part No: 141011040011-R; Package: UQFN16; Part_type: ICS\DIGITAL\BUSTRANSCEIVER; Project: HMC; RoHS: RoHS; Temperature: -40°C+85°C; Tolerance: NA; Voltage: NA; Wattage: NA; Weight: 41mg; Datasheet: Y:\MIS_DATABASE\DATASHEETS\ICS\DIGITAL\BUSTRANSCEIVER\SN74AVC4T245-SER.PDF
U25 = TCA9517DGKR_VSSOP8: IC 2-CHANNEL BI-DIR LEVEL-SHIFTING I2C BUS REPEATER SOIC8; Chkd/date: MANIRAJA/171121; Crtd /date: ALVY/161121; Custom_Duty: 15%; Customs_HS_Code: 85423100; Distributor_name: DIGIKEY; Distributor_part_number: 296-39221-1-ND; Footprint Path: Y:\MIS_DATABASE\Library\ALTIUM_TOOL\PCB_FOOTPRINTS\Altium_Footprint_Lib.PcbLib; Height: 1.75MM; Library Path: Y:\MIS_DATABASE\Library\ALTIUM_TOOL\SCHEMATICS_PARTS\MS_MISCINTERFACE_Library.schlib; Mfr_name: TEXAS INSTRUMENTS; Mistral Part No: 141021110017-R; Package: SOIC8; Part_type: ICS\INTERFACE\LEVEL TRANSLATOR; Project: EXCITER MULTI-CH RX UNIT; RoHS: RoHS; Temperature: -40°C+85°C; Tolerance: NA; Voltage: NA; Wattage: NA; Weight: 540mg; Datasheet: Y:\MIS_DATABASE\DATASHEETS\ICS\INTERFACE\TCA9517.PDF
U40 = 74HC7014X_SOIC14: IC HEX BUFFER AND DRIVER WITH OPEN DRAIN OUTPUT TVSOP14; Chkd/date: ALVY/070422; Crtd /date: TAMILARASU/070422; Custom_Duty: 15%; Customs_HS_Code: 85423100; Distributor_name: DIGIKEY; Distributor_part_number: 296-8440-1-ND; Footprint Path: Y:\MIS_DATABASE\Library\ALTIUM_TOOL\PCB_FOOTPRINTS\Altium_Footprint_Lib.PcbLib; Height: 1.20MM; Library Path: Y:\MIS_DATABASE\Library\ALTIUM_TOOL\SCHEMATICS_PARTS\MS_COMBINATIONAL_Library.schlib; Mfr_name: TEXAS INSTRUMENTS; Mistral Part No: 141022040005-R; Package: TVSOP14; Part_type: ICS\DIGITAL\COMBINATIONAL; Project: TI_AM62x_SKEVM_BRD; RoHS: RoHS; Temperature: -40°C+125°C; Tolerance: NA; Voltage: NA; Wattage: NA; Weight: 41.8mg; Datasheet: Y:\MIS_DATABASE\DATASHEETS\ICS\DIGITAL\COMBINATIONAL\SN74LVC07A.PDF
U51 = TXS0102DQX_SON8: IC 2-BIT BI-DIR VOLTAGE-LEVEL TRANSLATOR FOR OPEN-DRAIN AND PUSH-PULL X2SON8; Chkd/date: MANIRAJA/010719; Crtd /date: CHAITHANYA230512; Custom_Duty: 15%; Customs_HS_Code: 85423100; Distributor_name: DIGIKEY; Distributor_part_number: 296-28368-1-ND; Footprint Path: Y:\MIS_DATABASE\Library\ALTIUM_TOOL\PCB_FOOTPRINTS\Altium_Footprint_Lib.PcbLib; Height: 0.40MM; Library Path: Y:\MIS_DATABASE\Library\ALTIUM_TOOL\SCHEMATICS_PARTS\MS_MISCINTERFACE_Library.schlib; Mfr_name: TEXAS INSTRUMENTS; Mistral Part No: 141012050010-R; Package: X2SON8; Part_type: ICS\INTERFACE\LEVEL TRANSLATOR; Project: GEN_3-8_DB; RoHS: RoHS; Temperature: -40°C+85°C; Tolerance: NA; Voltage: NA; Wattage: NA; Weight: 1.2mg; Datasheet: Y:\MIS_DATABASE\DATASHEETS\ICS\INTERFACE\TXS0102-SER.PDF

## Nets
DGND: C83.2 C99.2 C101.2 C140.2 C147.2 C157.2 C162.2 C181.1 C192.2 C235.1 C236.1 C574.1 C575.1 C608.1 C612.1 C613.1 C617.1 C618.1 D13.1 Q2.2(EMITTER) Q3.2(S) R278.1 R591.1 R613.1 R635.1 SW7.1 SW7.4 U9.2(GND) U11.2(GND) U25.4(GND) U30.3(GND) U31.3(GND) U36.3(GND) U40.7(GND) U51.4(GND) U117.1(~{1OE}) U117.10(GND1) U117.11(GND2) U117.16(~{2OE}) U125.1(~{1OE}) U125.7(1A2) U125.9(2A2) U125.10(GND1) U125.11(GND2) U125.12(2B2) U125.14(1B2) U125.16(~{2OE}) U126.1(~{1OE}) U126.7(1A2) U126.9(2A2) U126.10(GND1) U126.11(GND2) U126.12(2B2) U126.14(1B2) U126.16(~{2OE}) ; also on sheet 5 6 7 8 9 10 12 13 14 16 17 18 19 20 21 22 31 32 33 34 35 36 37 38 39 40 41 42 43 44 45 46 47 48 49 50 51 52 53 54 55 56 57 58
VCC1V8_SYS: C101.1 C608.2 C617.2 R69.1 R164.2 R361.1 R611.1 R612.1 R614.2 R631.1 R636.2 U11.3(VCCA) U125.3(VCCA) U126.3(VCCA) ; also on sheet 6 7 10 20 21 22 33 37 38 39 42 43 49 50 52 53 54 55 56 57 58
VCC1V8_VDD18: C83.1 C157.1 C162.1 R53.2 R144.1 U9.4(VDD) U30.5(VCC) U31.5(VCC) ; also on sheet 49
VCC3V3_TA: C236.2 R285.1 R507.1 R511.1 R513.1 R516.1 R524.1 R526.1 U51.8(VCCB) ; also on sheet 9 43
VCC3V3_XDS: C147.1 C192.1 C235.2 R118.1 R119.1 R277.2 R280.1 R510.1 R512.1 R515.1 R517.1 R519.1 R525.1 U25.8(VCCB) U40.14(VCC) U51.1(VCCA) ; also on sheet 43 44 45
VCC_3V3_FT4232: C575.2 C612.2 C618.2 U117.2(VCCB) U125.2(VCCB) U126.2(VCCB) ; also on sheet 47
VCC_3V3_MAIN: R371.1 ; also on sheet 13 14 32 33 43
VCC_3V3_SYS: C99.1 C140.1 C181.2 R56.1 R58.1 R260.2 R292.2 U11.7(VCCB) U25.1(VCCA) U36.5(VCC) ; also on sheet 6 10 14 17 18 19 20 22 31 33 37 38 40 41 42 45 46 48 49 50 51 52 53 54 55 56 57 58
VDDR_CORE: R272.1 ; also on sheet 33 34 35
BUF_BOOTMODE_I2C0_SCL: R119.2 U25.7(SCLB) ; also on sheet 44
BUF_BOOTMODE_I2C0_SDA: R118.2 U25.6(SDAB) ; also on sheet 44
BUF_TEST_GPIO1: R519.2 U40.1(1A) ; also on sheet 44
BUF_TEST_GPIO2: R280.2 U51.2(A1) ; also on sheet 44
BUF_TEST_GPIO3: R515.2 U40.3(2A) ; also on sheet 44
BUF_TEST_GPIO4: R510.2 U40.5(3A) ; also on sheet 44
BUF_TEST_PORZn: R512.2 U40.9(4A) ; also on sheet 44
BUF_TEST_POWERDOWN: R525.2 U40.13(6A) ; also on sheet 44
BUF_TEST_WARMRESETn: R517.2 U40.11(5A) ; also on sheet 44
CAN_IO_3V3: C574.2 R322.1 R326.1 R590.2 R592.1 R593.1 U117.3(VCCA) ; also on sheet 13 33 34
CORE_CONFIG: R371.2 SW7.3 TP76.1(TP) ; also on sheet 33
CPLD_UART0_RXD: R361.2 TP97.1(TP) U126.8(2A1) ; also on sheet 20
CPLD_UART0_TXD: R631.2 TP117.1(TP) U126.6(1A1) ; also on sheet 20
DIX4192_McASP0_ACLKX: U31.4(Y) ; also on sheet 49
DIX4192_McASP0_AXR1: U30.4(Y) ; also on sheet 49
EXP1_McASP0_ACLKX: U31.2(A) ; also on sheet 7 54
EXP1_McASP0_AXR1: U30.2(A) ; also on sheet 7 54
FT4232_CPLD_UART0_RX_3V3: U126.13(2B1) ; also on sheet 47
FT4232_CPLD_UART0_TX_3V3: U126.15(1B1) ; also on sheet 47
FT4232_MCU_UART0_RX_3V3: U117.13(2B1) ; also on sheet 47
FT4232_MCU_UART0_TX_3V3: U117.15(1B1) ; also on sheet 47
FT4232_SOC_UART4_RX_3V3: U125.13(2B1) ; also on sheet 47
FT4232_SOC_UART4_TX_3V3: U125.15(1B1) ; also on sheet 47
FT4232_WKUP_UART0_RX_3V3: U117.12(2B2) ; also on sheet 47
FT4232_WKUP_UART0_TX_3V3: U117.14(1B2) ; also on sheet 47
GPIO2_BUF_EN: R277.1 R278.2 U51.5(OE)
MCU_UART0_RX_3V3: R326.2 U117.8(2A1) ; also on sheet 48
MCU_UART0_TX_3V3: R592.2 U117.6(1A1) ; also on sheet 48
PMIC_INTn: U36.2(A) ; also on sheet 33
PMIC_INTn_1V8: R164.1 U36.4(Y) ; also on sheet 10
PMIC_RSTOUT: R286.1 ; also on sheet 33
RXCKI: R39.2 ; also on sheet 49
RXCKI_OSC: R39.1 U9.3(OUT)
SoC_I2C0_SCL: R56.2 U11.8(SCL_B) U25.2(SCLA) ; also on sheet 17 20 22 40 41 50 55
SoC_I2C0_SCL_1V8: U11.5(SCL_A) ; also on sheet 5 7 21 49 50 53 56
SoC_I2C0_SDA: R58.2 U11.1(SDA_B) U25.3(SDAA) ; also on sheet 17 20 22 40 41 50 55
SoC_I2C0_SDA_1V8: U11.4(SDA_A) ; also on sheet 5 7 21 49 50 53 56
TEST_GPIO1: R235.1 R526.2 ; also on sheet 57
TEST_GPIO2: R283.1 R285.2 ; also on sheet 55
TEST_GPIO3: R227.1 R516.2 ; also on sheet 43
TEST_GPIO4: R221.1 R511.2 ; also on sheet 43
TEST_PORZn: R219.1 R507.2 ; also on sheet 10
TEST_POWERDOWN: R233.1 R524.2 ; also on sheet 32 33
TEST_WARMRESETn: R224.1 R513.2 ; also on sheet 57
UART4_RXD: R612.2 U125.8(2A1) ; also on sheet 7
UART4_TXD: R611.2 U125.6(1A1) ; also on sheet 7
WKUP_UART0_RX_3V3: R322.2 U117.9(2A2) ; also on sheet 48
WKUP_UART0_TX_3V3: R593.2 U117.7(1A2) ; also on sheet 48
XDS_GPIO1: R235.2 U40.2(1Y)
XDS_GPIO2: R283.2 U51.7(B1)
XDS_GPIO3: R227.2 U40.4(2Y)
XDS_GPIO4: R221.2 U40.6(3Y)
XDS_PORZn: R219.2 U40.8(4Y)
XDS_POWERDOWN: R233.2 U40.12(6Y)
XDS_WARMRESETn: R224.2 U40.10(5Y)
N27239473: R591.2 U117.5(2DIR)
N27239479: R590.1 U117.4(1DIR)
N27239926: R635.2 U126.5(2DIR)
N27239932: R636.1 U126.4(1DIR)
N27240077: R613.2 U125.5(2DIR)
N27240083: R614.1 U125.4(1DIR)
N27243596: TP61.1(TP) U51.6(B2)
N27243598: TP58.1(TP) U51.3(A2)
N27566274: LD2.1(CATHODE) Q2.3(COLLECTOR)
N27566278: LD2.2(ANODE) R260.1
N27566306: Q2.1(BASE) R272.2
N27566380: LD4.2(ANODE) R292.1
N27566388: LD4.1(CATHODE) Q3.3(D)
N27566452: C613.2 D13.2 SW7.2
N27570222: R144.2 U30.1(OE) U31.1(OE)
N27570724: R69.2 U11.6(OE)
N27571220: R53.1 U9.1(OE/NC)
N27680812: Q3.1(G) R286.2

Not connected (* = marked no-connect by the designer): U25 5(EN)*; U36 1(NC)*

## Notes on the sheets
sheet 1
- AUDIO -  DIGITAL IN & OUT, OPTICAL IN - 2
- BUFFERS  FOR DIX4192
- DIX4192 CLOCKING
- I2C LEVEL TRANSLATOR
sheet 2
- SOC POWER SUPPLY PMIC - 2
- PMIC POWER INDICATION LED
- VBE = 0.85V
  Ic = 20mA
  Ib = 0.2mA
- PMIC PUSH BUTTON LOGIC
- PMIC INT SCHMIT TRIGGER
- Silk: PMIC_CORE_CONFIG
- Note: When R371 is DNI, Push Button (SW 7) becomes
  operational through internal pullup on PMIC GPIO3
- R371
- VDD_CORE VOLTAGE
- Mounted
- 0.85 V (DEFAULT)
- Not Mounted
- 0.75 V
sheet 3
- XDS110 TEST AUTOMATION BUFFERS
- This pulls provides a
  defined logic state to the
  Test Automation signals
  before XDS110 firmware is loaded
- Open Drain Buffer
  for Test Automation
  using XDS110
- This pulldown provides a
  defined logic state when
  VCC3V3_XDS is not sourced
- Bidirectional Translator
  for Test Automation
  using XDS110
- SOC I2C BUS BUFFER
- TCA9517DR has internal
  Pullup resistors
sheet 4
- FT4232 UART BUFFERS
